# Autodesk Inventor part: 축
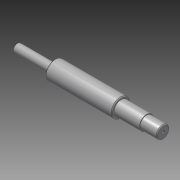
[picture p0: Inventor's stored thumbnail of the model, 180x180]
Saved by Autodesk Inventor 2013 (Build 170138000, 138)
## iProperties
Created: 2016-05
Part Number: 축
Document SubType Name: Modeling
Designer: mduedu
Density: 7.86 g/cm^3
Material: 강철, 연강
Author: mduedu
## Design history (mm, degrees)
sketch "스케치1"
  geometry: L1 (-42, 11)-(-42, 5); L2 (37, 11)-(37, 8.5); L3 (-87, 0)-(87, 0); L4 (-42, 11)-(37, 11); L5 (37, 11)-(37, 8.5); L6 (-42, 11)-(-42, 5); L7 (-42, 5)-(-87, 5); L8 (-87, 5)-(-87, 0); L9 (37, 8.5)-(67, 8.5); L10 (87, 7.5)-(87, 0); L11 (67, 8.5)-(67, 7.5); L12 (67, 7.5)-(87, 7.5); 1 further point
  constraints: 24 end point, 9 perpendicular, 2 midpoint, 1 horizontal
  dimensions: "d0" = 22 diameter of L4 L3; "d1" = 10 diameter of L7 L3; "d2" = 45 distance between parallel lines of L8 L1; "d3" = 50 distance between parallel lines of L10 L2; "d4" = 15 diameter of L12 L3; "d5" = 20 distance between parallel lines of L10 L11; "d29" = 79 distance of L1.start L2.start; "d37" = 17 diameter of L9 L3
revolve "회전1" stored, may be unused: angle "d6" = 90 deg
chamfer "모따기2" distance "d32" = 1; stored, may be unused: second distance "d33" = 2, angle "d34" = 45 deg
node "작업 평면4"
sketch "스케치4"
  geometry: L1 (-5, 2.5)-(5, 2.5); L2 (5, -2.5)-(-5, -2.5); L3 (-10, -6.5)-(-10, 6.5) reference; A1 r 2.5 centre (5, 0) between (5, -2.5) and (5, 2.5); A2 r 2.5 centre (-5, 0) between (-5, 2.5) and (-5, -2.5); 1 further point
  constraints: 4 end point, 4 point on circle, 4 tangent, 2 centre point, 1 horizontal, 1 horizontal alignment, 1 parallel
  dimensions: "d20" = 5 distance between parallel lines of L2 L1; "d21" = 15 dimension on A1 A2; "d35" = 2.5 distance edge to line of A2 L3
extrude "돌출3" cut sketch "스케치4" distance "d23" = 3; taper "d24" = 0 deg
node "작업 평면5"
sketch "스케치5"
  geometry: L1 (22.5, 1.5)-(10, 1.5); L2 (10, -1.5)-(22.5, -1.5); L3 (22.5, 4)-(22.5, -4) reference; A1 r 1.5 centre (10, 0) between (10, 1.5) and (10, -1.5); 3 further points
  constraints: 4 end point, 2 horizontal alignment, 2 point on circle, 2 point on line, 2 tangent, 1 centre point, 1 coincident, 1 horizontal, 1 midpoint
  dimensions: "d25" = 3 distance between parallel lines of L2 L1; "d36" = 14 dimension on A1 L3
extrude "돌출4" cut sketch "스케치5" distance "d27" = 1.8; taper "d28" = 0 deg
hole "구멍1" diameter "d40" = 3.242; stored, may be unused: countersink angle "d44" = 90 deg, drill point angle "d46" = 118 deg; dims "d41" = 10, "d42" = 4, "d43" = 2, "d45" = 12, "d47" = 10, "d48" = 10
node "솔리드1"
